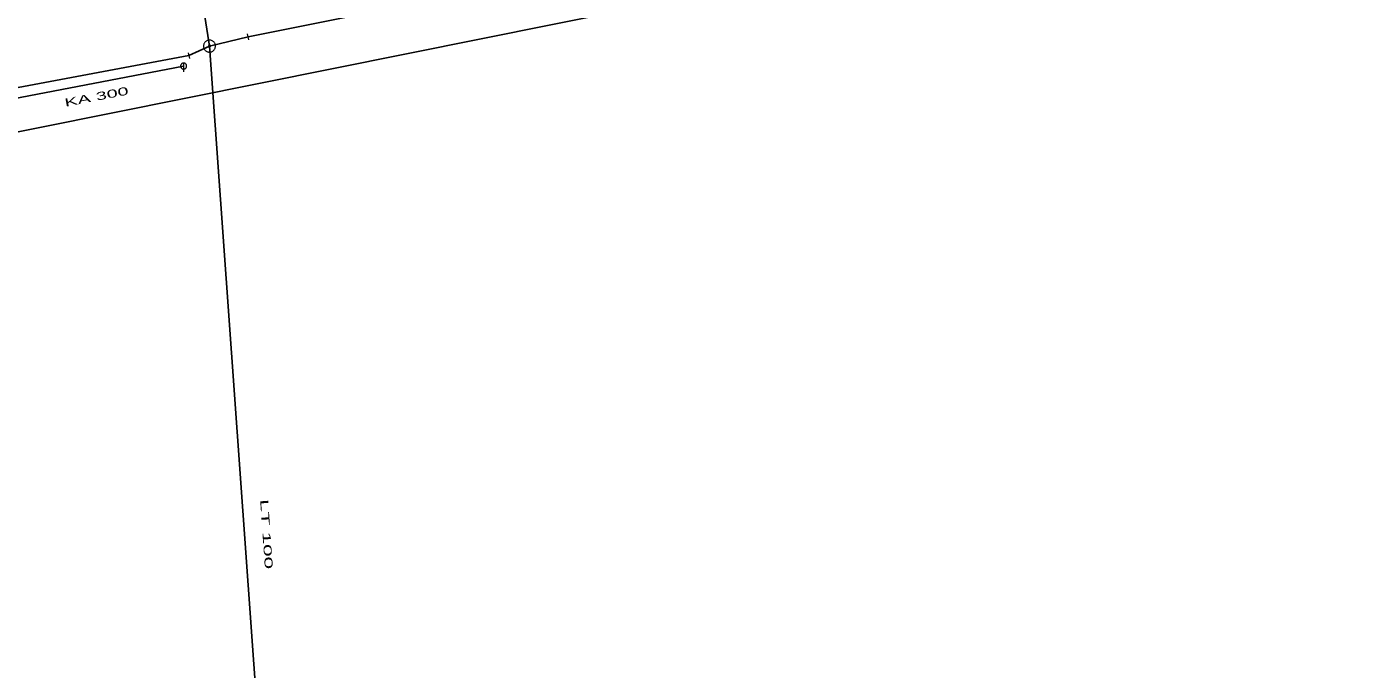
# Model space of a CAD drawing. Extents: x -687515 to -686506, y -974029 to -973461.
# Drawn here: x -687389.5 to -687277.4, y -973678.4 to -973624.9 of the extents above; entities that cross this region are included whole.
import ezdxf
from ezdxf.enums import TextEntityAlignment as Align

# ---------------------------------------------------------------- set-up
doc = ezdxf.new("R2010")
doc.units = 0
doc.header["$LTSCALE"] = 0.27
for name, color, linetype, lineweight in [('1', 7, 'Continuous', 13), ('14', 7, 'Continuous', 25), ('17', 7, 'Continuous', 25), ('22', 7, 'Continuous', 13), ('34', 7, 'Continuous', 13), ('47', 7, 'Continuous', 13)]:
    doc.layers.add(name, color=color, linetype=linetype, lineweight=lineweight)

msp = doc.modelspace()

# ---------------------------------------------------------------- linework, layer by layer
at = {"layer": '14'}
msp.add_line((-687376.437, -973628.208), (-687391.359, -973631.065), dxfattribs=at)
at = {"layer": '17'}
for p, q in [((-687375.989, -973627.339), (-687374.281, -973626.545)), ((-687456.678, -973642.368), (-687375.989, -973627.339))]:
    msp.add_line(p, q, dxfattribs=at)
for points in [[(-686645.309, -973464.46), (-686646.34, -973464.75), (-686680.188, -973471.317), (-686771.188, -973470.317), (-686761.188, -973557.317), (-686894.188, -973571.317), (-686953.188, -973578.317), (-686955.188, -973554.317), (-687116.188, -973577.317), (-687229.188, -973601.317), (-687468.188, -973649.317), (-687458.188, -973700.317)], [(-687374.281, -973626.545), (-687378.392, -973600.397), (-687384.642, -973565.265)], [(-687371.058, -973625.778), (-687263.409, -973604.207), (-687252.347, -973602.057)], [(-687368.281, -973710.084), (-687374.281, -973626.545), (-687371.058, -973625.778)]]:
    msp.add_lwpolyline(points, dxfattribs=at)
at = {"layer": '22'}
msp.add_line((-687376.436, -973627.956), (-687376.437, -973628.7), dxfattribs=at)
msp.add_lwpolyline([(-687376.185, -973628.208), (-687376.186, -973628.182), (-687376.19, -973628.156), (-687376.196, -973628.13), (-687376.206, -973628.106), (-687376.218, -973628.082), (-687376.232, -973628.06), (-687376.249, -973628.039), (-687376.267, -973628.021), (-687376.288, -973628.004), (-687376.31, -973627.99), (-687376.334, -973627.978), (-687376.358, -973627.968), (-687376.384, -973627.962), (-687376.41, -973627.958), (-687376.436, -973627.956), (-687376.462, -973627.957), (-687376.488, -973627.961), (-687376.514, -973627.967), (-687376.539, -973627.977), (-687376.562, -973627.989), (-687376.584, -973628.003), (-687376.605, -973628.02), (-687376.623, -973628.038), (-687376.64, -973628.059), (-687376.654, -973628.081), (-687376.666, -973628.105), (-687376.676, -973628.129), (-687376.683, -973628.155), (-687376.687, -973628.181), (-687376.689, -973628.207), (-687376.688, -973628.233), (-687376.684, -973628.259), (-687376.677, -973628.285), (-687376.667, -973628.31), (-687376.655, -973628.333), (-687376.641, -973628.355), (-687376.624, -973628.376), (-687376.606, -973628.394), (-687376.585, -973628.411), (-687376.563, -973628.425), (-687376.54, -973628.437), (-687376.515, -973628.447), (-687376.489, -973628.454), (-687376.463, -973628.458), (-687376.437, -973628.46), (-687376.411, -973628.459), (-687376.385, -973628.455), (-687376.359, -973628.448), (-687376.335, -973628.438), (-687376.311, -973628.426), (-687376.289, -973628.412), (-687376.268, -973628.395), (-687376.25, -973628.377), (-687376.233, -973628.356), (-687376.219, -973628.334), (-687376.207, -973628.311), (-687376.197, -973628.286), (-687376.191, -973628.26), (-687376.187, -973628.234)], close=True, dxfattribs=at)
at = {"layer": '34'}
for p, q in [((-687371.002, -973626.019), (-687371.113, -973625.536)), ((-687375.933, -973627.58), (-687376.044, -973627.097))]:
    msp.add_line(p, q, dxfattribs=at)
at = {"layer": '47'}
for points in [[(-687374.198, -973627.038), (-687374.147, -973627.026), (-687374.097, -973627.01), (-687374.05, -973626.988), (-687374.005, -973626.962), (-687373.963, -973626.93), (-687373.924, -973626.895), (-687373.89, -973626.855), (-687373.86, -973626.813), (-687373.834, -973626.768), (-687373.812, -973626.72), (-687373.796, -973626.669), (-687373.787, -973626.618), (-687373.781, -973626.567), (-687373.782, -973626.514), (-687373.787, -973626.462), (-687373.799, -973626.411), (-687373.815, -973626.361), (-687373.837, -973626.313), (-687373.863, -973626.269), (-687373.895, -973626.227), (-687373.93, -973626.188), (-687373.97, -973626.153), (-687374.012, -973626.123), (-687374.057, -973626.097), (-687374.105, -973626.076), (-687374.156, -973626.06), (-687374.207, -973626.05), (-687374.258, -973626.045), (-687374.311, -973626.046), (-687374.363, -973626.051), (-687374.414, -973626.063), (-687374.464, -973626.079), (-687374.512, -973626.101), (-687374.556, -973626.127), (-687374.598, -973626.159), (-687374.637, -973626.193), (-687374.672, -973626.233), (-687374.703, -973626.275), (-687374.728, -973626.321), (-687374.749, -973626.369), (-687374.765, -973626.42), (-687374.776, -973626.47), (-687374.78, -973626.522), (-687374.779, -973626.575), (-687374.774, -973626.627), (-687374.762, -973626.678), (-687374.746, -973626.728), (-687374.725, -973626.775), (-687374.698, -973626.82), (-687374.666, -973626.862), (-687374.632, -973626.901), (-687374.592, -973626.935), (-687374.55, -973626.966), (-687374.504, -973626.991), (-687374.456, -973627.013), (-687374.405, -973627.029), (-687374.355, -973627.039), (-687374.303, -973627.044), (-687374.25, -973627.043)], [(-687374.267, -973626.625), (-687374.258, -973626.624), (-687374.251, -973626.621), (-687374.243, -973626.617), (-687374.236, -973626.613), (-687374.228, -973626.608), (-687374.222, -973626.602), (-687374.216, -973626.596), (-687374.211, -973626.589), (-687374.207, -973626.581), (-687374.204, -973626.573), (-687374.201, -973626.565), (-687374.199, -973626.556), (-687374.199, -973626.548), (-687374.198, -973626.54), (-687374.2, -973626.531), (-687374.201, -973626.522), (-687374.204, -973626.515), (-687374.208, -973626.507), (-687374.212, -973626.5), (-687374.217, -973626.492), (-687374.223, -973626.486), (-687374.229, -973626.48), (-687374.236, -973626.475), (-687374.244, -973626.471), (-687374.252, -973626.468), (-687374.26, -973626.465), (-687374.269, -973626.463), (-687374.277, -973626.463), (-687374.285, -973626.462), (-687374.294, -973626.464), (-687374.303, -973626.465), (-687374.31, -973626.468), (-687374.318, -973626.472), (-687374.325, -973626.476), (-687374.333, -973626.481), (-687374.339, -973626.486), (-687374.345, -973626.493), (-687374.35, -973626.5), (-687374.354, -973626.508), (-687374.357, -973626.516), (-687374.36, -973626.524), (-687374.362, -973626.533), (-687374.362, -973626.541), (-687374.363, -973626.549), (-687374.361, -973626.558), (-687374.36, -973626.567), (-687374.357, -973626.574), (-687374.353, -973626.582), (-687374.349, -973626.589), (-687374.344, -973626.597), (-687374.339, -973626.603), (-687374.332, -973626.609), (-687374.325, -973626.614), (-687374.317, -973626.618), (-687374.309, -973626.621), (-687374.301, -973626.624), (-687374.292, -973626.626), (-687374.284, -973626.626), (-687374.276, -973626.627)]]:
    msp.add_lwpolyline(points, close=True, dxfattribs=at)

# ---------------------------------------------------------------- texts
at = {"layer": '1'}
for s, rotation, width, p in [('KA 300', 11, 1.85, (-687383.634, -973631.082)), ('LT 100', 274, 2.1, (-687369.862, -973667.191))]:
    msp.add_text(s, height=0.6667, rotation=rotation, dxfattribs=dict(at, width=width)).set_placement(p, align=Align.CENTER)

doc.saveas('drawing.dxf')
